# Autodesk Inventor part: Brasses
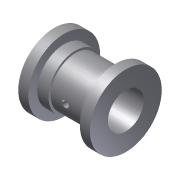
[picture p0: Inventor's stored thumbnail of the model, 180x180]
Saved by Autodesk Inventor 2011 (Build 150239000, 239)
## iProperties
Created: 2009-04
Part Number: Brasses
Document SubType Name: Modeling
Designer: Sham
Density: 1 g/cm^3
Author: Sham
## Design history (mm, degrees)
sketch "Sketch1"
  geometry: L1 (0, 32)-(9, 32); L2 (0, 16)-(64, 16); L3 (64, 32)-(55, 32); L4 (55, 32)-(55, 24); L5 (55, 24)-(47, 24); L6 (19, 22)-(47, 22); L7 (47, 24)-(47, 22); L8 (19, 22)-(19, 24); L9 (19, 24)-(9, 24); L10 (9, 24)-(9, 32); L11 (0, 32)-(0, 16); L12 (64, 32)-(64, 16); L13 (-12.8, 0)-(76.8, 0) reference; 1 further point
  constraints: 24 end point, 7 parallel, 4 perpendicular, 1 collinear, 1 horizontal, 1 vertical alignment, 1 other
  dimensions: "d0" = 9 distance of L1.start L1.end; "d2" = 16 distance from line of L2 point (0, 0); "d3" = 64 distance of L2.start L2.end; "d4" = 24 distance from line of point (0, 0) L5; "d5" = 28 distance of L6.start L6.end; "d6" = 22 distance from line of point (0, 0) L6; "d7" = 8 distance of L4.end L5.end
revolve "Revolution1" sketch "Sketch1" stored, may be unused: angle "d8" = 90 deg
workplane "Work Plane1"
sketch "Sketch2"
  geometry: C1 r 4 at (-32, 0)
  constraints: 1 centre point
  dimensions: "d10" = 8 diameter of C1
extrude "Extrusion1" join sketch "Sketch2" stored distance "d11" = 10; taper "d12" = 0 deg
sketch "Sketch3"
  geometry: C1 r 4 at (0, 0) reference; C2 r 3 at (0, 0)
  constraints: 1 centre point, 1 coincident
  dimensions: "d13" = 6 diameter of C2
extrude "Extrusion2" cut sketch "Sketch3" stored distance "d14" = 10; taper "d15" = 0 deg
body "Solid1"
